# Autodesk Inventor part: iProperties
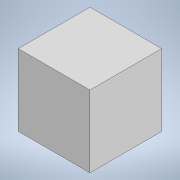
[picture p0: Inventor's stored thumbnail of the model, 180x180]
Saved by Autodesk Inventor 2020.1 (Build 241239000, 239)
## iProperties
Created: 2019-11
Part Number: iProperties
Material: Generic
Document SubType Name: Modeling
Designer: Synergysoft Dell02
Density: 1 g/cm^3
Appearance: Default
Author: Synergysoft Dell02
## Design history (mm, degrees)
sketch "Sketch1"
  geometry: L1 (25, 25)-(-25, 25); L2 (-25, 25)-(-25, -25); L3 (-25, -25)-(25, -25); L4 (25, -25)-(25, 25); L5 (25, 25)-(-25, -25); L6 (-25, 25)-(25, -25); 1 further point
  constraints: 12 end point, 2 midpoint, 2 parallel, 1 horizontal, 1 perpendicular
  dimensions: "d0" = 50 distance of L3.end L2.end; "d1" = 50 distance of L2.end L1.end
extrude "Extrusion1" new body sketch "Sketch1" distance "d2" = 50; taper "d3" = 0 deg
body "Solid1"
